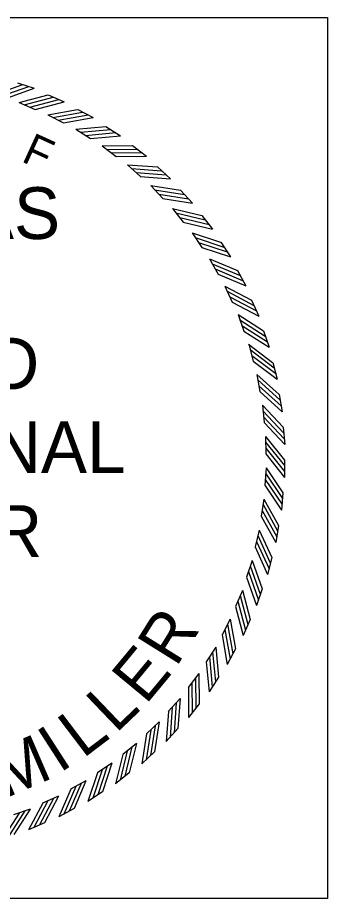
# Model space of a CAD drawing. Extents: x 0 to 1228740, y 0 to 152440.
# Drawn here: x 32.457 to 33.423, y 22.685 to 25.435 of the extents above; entities that cross this region are included whole.
import ezdxf

# ---------------------------------------------------------------- set-up
doc = ezdxf.new("R2010")
doc.units = 0
doc.layers.add('R_No Plot', color=7, linetype='Continuous')
doc.layers.add('STAMP_LKM', color=7, linetype='Continuous')

msp = doc.modelspace()

# ---------------------------------------------------------------- linework, layer by layer
at = {"layer": 'R_No Plot'}
msp.add_lwpolyline([(30.6731, 25.4352), (33.4231, 25.4352), (33.4231, 22.6852), (30.6731, 22.6852)], close=True, dxfattribs=at)
at = {"layer": 'STAMP_LKM'}
for p, q in [((32.457, 25.2317), (32.5087, 25.2145)), ((32.5524, 25.194), (32.6024, 25.1726)), ((32.4614, 25.1699), (32.5115, 25.1485)), ((32.6443, 25.1485), (32.6924, 25.123)), ((32.5516, 25.132), (32.5998, 25.1065)), ((32.6384, 25.0868), (32.6843, 25.0574)), ((32.7321, 25.0955), (32.7779, 25.0662)), ((32.7211, 25.0345), (32.7645, 25.0014)), ((32.8153, 25.0355), (32.8585, 25.0025)), ((32.7993, 24.9756), (32.8398, 24.9391)), ((32.8932, 24.9688), (32.9336, 24.9323)), ((32.8723, 24.9105), (32.9096, 24.8707)), ((32.9654, 24.8959), (33.0026, 24.8562)), ((32.9397, 24.8395), (32.9736, 24.7968)), ((33.0312, 24.8173), (33.0651, 24.7747)), ((33.0011, 24.7632), (33.0313, 24.7178)), ((33.0904, 24.7336), (33.1206, 24.6883)), ((33.0559, 24.6821), (33.0823, 24.6344)), ((33.1425, 24.6452), (33.1688, 24.5976)), ((33.1038, 24.5968), (33.1261, 24.547)), ((33.187, 24.5528), (33.2093, 24.5032)), ((33.1445, 24.5078), (33.1627, 24.4564)), ((33.2238, 24.4571), (33.242, 24.4058)), ((33.1777, 24.4157), (33.1916, 24.363)), ((33.2526, 24.3586), (33.2664, 24.306)), ((33.2032, 24.3212), (33.2127, 24.2675)), ((33.2731, 24.2582), (33.2826, 24.2046)), ((33.2208, 24.2249), (33.2258, 24.1706)), ((33.2853, 24.1563), (33.2903, 24.1021)), ((33.2304, 24.1275), (33.2309, 24.073)), ((33.289, 24.0538), (33.2895, 23.9994)), ((33.232, 24.0297), (33.228, 23.9753)), ((33.2254, 23.932), (33.2169, 23.8781)), ((33.2842, 23.9514), (33.2803, 23.8971)), ((33.271, 23.8497), (33.2626, 23.7959)), ((33.2108, 23.8352), (33.1979, 23.7823)), ((33.1882, 23.74), (33.171, 23.6883)), ((33.2495, 23.7494), (33.2366, 23.6965)), ((33.2197, 23.6513), (33.2025, 23.5996)), ((33.1579, 23.6469), (33.1365, 23.5968)), ((33.12, 23.5567), (33.0945, 23.5085)), ((33.1819, 23.5559), (33.1606, 23.5059)), ((33.0748, 23.4699), (33.0454, 23.424)), ((33.1364, 23.464), (33.111, 23.4159)), ((33.0225, 23.3871), (32.9894, 23.3438)), ((33.0835, 23.3762), (33.0541, 23.3303)), ((32.9636, 23.309), (32.927, 23.2685)), ((33.0235, 23.293), (32.9904, 23.2498)), ((32.8985, 23.236), (32.8587, 23.1986)), ((32.9568, 23.2151), (32.9203, 23.1747)), ((32.8275, 23.1685), (32.7848, 23.1347)), ((32.8839, 23.1429), (32.8442, 23.1057)), ((32.7512, 23.1072), (32.7058, 23.077)), ((32.8053, 23.077), (32.7627, 23.0432)), ((32.6701, 23.0524), (32.6224, 23.026)), ((32.7215, 23.0179), (32.6763, 22.9877)), ((32.5848, 23.0045), (32.535, 22.9821)), ((32.4958, 22.9638), (32.4443, 22.9456)), ((32.6332, 22.9658), (32.5855, 22.9395)), ((32.5408, 22.9213), (32.4912, 22.8989))]:
    msp.add_line(p, q, dxfattribs=at)
for points in [[(32.3848, 25.1946), (32.4735, 25.226)], [(32.4028, 25.189), (32.4916, 25.2205)], [(32.42, 25.1831), (32.5087, 25.2146)], [(32.4613, 25.1699), (32.5523, 25.194)], [(32.4773, 25.1629), (32.5683, 25.1869)], [(32.4949, 25.1558), (32.5859, 25.1799)], [(32.5114, 25.1486), (32.6025, 25.1726)], [(32.5515, 25.132), (32.6442, 25.1485)], [(32.5669, 25.1237), (32.6596, 25.1401)], [(32.5838, 25.1152), (32.6765, 25.1316)], [(32.5997, 25.1066), (32.6924, 25.123)], [(32.6383, 25.0868), (32.732, 25.0955)], [(32.653, 25.0772), (32.7467, 25.0859)], [(32.6691, 25.0674), (32.7628, 25.0761)], [(32.6843, 25.0575), (32.778, 25.0662)], [(32.7211, 25.0345), (32.8152, 25.0355)], [(32.7349, 25.0238), (32.829, 25.0247)], [(32.7502, 25.0126), (32.8443, 25.0136)], [(32.7645, 25.0015), (32.8586, 25.0025)], [(32.7992, 24.9756), (32.8931, 24.9688)], [(32.8121, 24.9638), (32.906, 24.957)], [(32.8264, 24.9514), (32.9203, 24.9446)], [(32.8397, 24.9391), (32.9336, 24.9323)], [(32.8723, 24.9105), (32.9653, 24.8959)], [(32.8841, 24.8976), (32.9771, 24.8831)], [(32.8974, 24.8841), (32.9904, 24.8696)], [(32.9096, 24.8708), (33.0026, 24.8562)], [(32.9397, 24.8395), (33.0312, 24.8174)], [(32.9504, 24.8257), (33.0419, 24.8035)], [(32.9625, 24.8112), (33.054, 24.789)], [(32.9736, 24.7969), (33.0651, 24.7747)], [(33.001, 24.7632), (33.0903, 24.7336)], [(33.0106, 24.7486), (33.0999, 24.7189)], [(33.0214, 24.7331), (33.1107, 24.7034)], [(33.0313, 24.7179), (33.1206, 24.6883)], [(33.0558, 24.6822), (33.1424, 24.6452)], [(33.0641, 24.6668), (33.1507, 24.6298)], [(33.0736, 24.6504), (33.1602, 24.6135)], [(33.0823, 24.6345), (33.1689, 24.5975)], [(33.1037, 24.5968), (33.187, 24.5529)], [(33.1107, 24.5808), (33.194, 24.5368)], [(33.1189, 24.5637), (33.2021, 24.5198)], [(33.1262, 24.5471), (33.2094, 24.5032)], [(33.1444, 24.5078), (33.2238, 24.4571)], [(33.1501, 24.4913), (33.2294, 24.4406)], [(33.1568, 24.4736), (33.2361, 24.4229)], [(33.1627, 24.4564), (33.242, 24.4058)], [(33.1776, 24.4158), (33.2525, 24.3587)], [(33.1819, 24.3988), (33.2568, 24.3417)], [(33.1872, 24.3806), (33.262, 24.3236)], [(33.1916, 24.363), (33.2665, 24.306)], [(33.2032, 24.3213), (33.2731, 24.2582)], [(33.206, 24.304), (33.2759, 24.2409)], [(33.2097, 24.2855), (33.2796, 24.2224)], [(33.2127, 24.2676), (33.2826, 24.2045)], [(33.2208, 24.225), (33.2852, 24.1564)], [(33.2222, 24.2075), (33.2867, 24.1389)], [(33.2244, 24.1888), (33.2888, 24.1202)], [(33.2259, 24.1707), (33.2903, 24.1021)], [(33.2304, 24.1276), (33.289, 24.0539)], [(33.2304, 24.1101), (33.289, 24.0364)], [(33.231, 24.0912), (33.2895, 24.0175)], [(33.231, 24.0731), (33.2895, 23.9994)], [(33.2305, 24.0123), (33.2828, 23.934)], [(33.2319, 24.0297), (33.2842, 23.9515)], [(33.2295, 23.9934), (33.2818, 23.9151)], [(33.228, 23.9753), (33.2803, 23.8971)], [(33.2254, 23.9321), (33.271, 23.8498)], [(33.2225, 23.9148), (33.2681, 23.8325)], [(33.217, 23.8782), (33.2626, 23.7959)], [(33.2199, 23.8961), (33.2656, 23.8138)], [(33.2065, 23.8183), (33.2452, 23.7325)], [(33.2108, 23.8353), (33.2494, 23.7495)], [(33.2024, 23.7999), (33.2411, 23.7141)], [(33.1979, 23.7823), (33.2366, 23.6965)], [(33.1882, 23.7401), (33.2197, 23.6513)], [(33.177, 23.7054), (33.2084, 23.6167)], [(33.1825, 23.7235), (33.214, 23.6348)], [(33.1711, 23.6883), (33.2025, 23.5996)], [(33.1509, 23.631), (33.1749, 23.54)], [(33.1579, 23.647), (33.1819, 23.556)], [(33.1365, 23.5968), (33.1606, 23.5058)], [(33.1438, 23.6134), (33.1678, 23.5224)], [(33.1117, 23.5414), (33.1281, 23.4487)], [(33.12, 23.5568), (33.1364, 23.4641)], [(33.1032, 23.5245), (33.1196, 23.4318)], [(33.0946, 23.5085), (33.111, 23.4159)], [(33.0748, 23.47), (33.0835, 23.3763)], [(33.0553, 23.4392), (33.0641, 23.3455)], [(33.0652, 23.4553), (33.0739, 23.3616)], [(33.0454, 23.424), (33.0542, 23.3303)], [(33.0225, 23.3872), (33.0235, 23.2931)], [(33.0006, 23.3581), (33.0016, 23.264)], [(33.0118, 23.3734), (33.0127, 23.2793)], [(32.9895, 23.3438), (32.9904, 23.2497)], [(32.9518, 23.2962), (32.9449, 23.2023)], [(32.9636, 23.3091), (32.9568, 23.2152)], [(32.9271, 23.2685), (32.9203, 23.1747)], [(32.9394, 23.2819), (32.9326, 23.188)], [(32.8721, 23.2109), (32.8575, 23.1179)], [(32.8856, 23.2242), (32.871, 23.1312)], [(32.8985, 23.236), (32.8839, 23.143)], [(32.8587, 23.1987), (32.8442, 23.1057)], [(32.8137, 23.1579), (32.7915, 23.0664)], [(32.8275, 23.1686), (32.8053, 23.0771)], [(32.7848, 23.1347), (32.7627, 23.0432)], [(32.7991, 23.1458), (32.777, 23.0543)], [(32.7512, 23.1073), (32.7216, 23.018)], [(32.7059, 23.077), (32.6762, 22.9876)], [(32.7211, 23.0869), (32.6914, 22.9976)], [(32.7366, 23.0977), (32.7069, 23.0084)], [(32.6701, 23.0525), (32.6332, 22.9659)], [(32.6225, 23.026), (32.5855, 22.9394)], [(32.6384, 23.0347), (32.6015, 22.9481)], [(32.6547, 23.0442), (32.6178, 22.9576)], [(32.5688, 22.9975), (32.5248, 22.9143)], [(32.5848, 23.0046), (32.5408, 22.9213)], [(32.4958, 22.9639), (32.4451, 22.8845)], [(32.5351, 22.9821), (32.4911, 22.8989)], [(32.5517, 22.9894), (32.5077, 22.9062)], [(32.4616, 22.9515), (32.4109, 22.8722)], [(32.4792, 22.9582), (32.4285, 22.8789)]]:
    msp.add_lwpolyline(points, dxfattribs=at)

# ---------------------------------------------------------------- texts
for s, height, rotation, p in [('F', 0.099, 335.3628, (32.4652, 24.9876)), ('R', 0.1504, 57.9868, (32.9512, 23.4041)), ('E', 0.1504, 50.326, (32.8562, 23.2873)), ('L', 0.1504, 43.7596, (32.763, 23.198)), ('L', 0.1504, 37.1932, (32.6602, 23.12)), ('I', 0.1504, 32.8156, (32.587, 23.0747)), ('M', 0.1504, 23.3308, (32.4179, 22.9966))]:
    msp.add_text(s, height=height, rotation=rotation, dxfattribs=at).set_placement(p)
for s, height, p in [('ARKANSAS', 0.16155, (31.4131, 24.744)), ('LICENSED', 0.16155, (31.4439, 24.2744)), ('PROFESSIONAL', 0.161547, (31.1131, 24.0129)), ('ENGINEER', 0.16155, (31.4054, 23.7513))]:
    msp.add_text(s, height=height, dxfattribs=at).set_placement(p)

doc.saveas('drawing.dxf')
